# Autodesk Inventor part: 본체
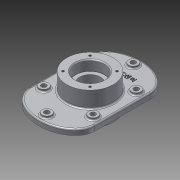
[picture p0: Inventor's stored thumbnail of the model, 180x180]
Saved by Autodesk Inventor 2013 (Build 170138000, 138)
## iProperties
Created: 2015-02
Part Number: 본체
Material: 알루미늄 6061
Document SubType Name: Modeling
Designer: Administrator
Density: 2.71 g/cm^3
Mass: 1660.48 g
Surface Area: 940.405 cm^2
Volume: 612.722 cm^3
Author: Administrator
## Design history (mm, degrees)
sketch "스케치1" dims "d8" = 70, "d10" = 50, "d11" = 50
  geometry: L1 (70, 60)-(70, -60); L2 (-70, -60)-(-70, 60); 5 further points; 2 other entities
  constraints: 4 end point, 2 horizontal alignment, 2 midpoint, 2 vertical alignment, 1 parallel, 8 other
  dimensions: "d5" = 140 distance between parallel lines of L1 L2; "d7" = 120 distance of point (0, 60) point (0, -60); "d133" = 60 distance of point (0, 0) point (0, 60); "d134" = 60 distance of point (0, 0) point (0, -60) (derived)
extrude "돌출1" new body sketch "스케치1" distance "d12" = 12; taper "d13" = 0 deg
sketch "스케치2"
  geometry: C1 r 50 at (0, 0); 1 further point
  constraints: 1 centre point, 1 coincident
  dimensions: "d14" = 100 diameter of C1
extrude "돌출2" join sketch "스케치2" distance "d15" = 35; taper "d16" = 0 deg
sketch "스케치3"
  geometry: C1 r 50 at (0, 0); 1 further point
  constraints: 1 centre point, 1 coincident
  dimensions: "d17" = 100 diameter of C1
extrude "돌출3" join sketch "스케치3" distance "d18" = 23; taper "d19" = 0 deg
sketch "스케치4"
  geometry: L1 (-70, 60)-(-70, -60) reference; L2 (70, -60)-(70, 60) reference; L3 (-53, 60)-(-53, -60); L4 (53, -60)-(53, 60); C1 r 50 at (0, 0) reference; C2 r 10 at (0, 93); C3 r 10 at (-53, 46.5); C4 r 10 at (-53, -46.5); C5 r 10 at (0, -93); C6 r 10 at (53, -46.5); C7 r 10 at (53, 46.5); 2 further points; 2 other entities
  constraints: 6 centre point, 4 end point, 3 parallel, 1 horizontal alignment, 1 vertical alignment, 9 other
  dimensions: "d20" = 17 distance between parallel lines of L2 L4; "d21" = 20 diameter of C2; "d24" = 360 deg dimension on C1.centre C2.centre (derived); "d26" = 17 distance from line of L2 C7.centre; "d27" = 17 distance from line of L2 C6.centre; "d28" = 17 distance from line of L1 C4.centre; "d29" = 17 distance from line of L1 C3.centre
extrude "돌출4" join sketch "스케치4" distance "d30" = 5; taper "d31" = 0 deg
hole "구멍1" diameter "d34" = 11; stored, may be unused: countersink angle "d38" = 90 deg, drill point angle "d40" = 0 deg; dims "d32" = 10, "d33" = 10, "d35" = 6, "d36" = 4, "d37" = 2, "d39" = 8
hole "구멍2" diameter "d43" = 11; stored, may be unused: countersink angle "d47" = 90 deg, drill point angle "d49" = 0 deg; dims "d41" = 10, "d42" = 10, "d44" = 6, "d45" = 4, "d46" = 2, "d48" = 8
hole "구멍3" diameter "d52" = 11; stored, may be unused: countersink angle "d56" = 90 deg, drill point angle "d58" = 0 deg; dims "d50" = 10, "d51" = 10, "d53" = 6, "d54" = 4, "d55" = 2, "d57" = 8
hole "구멍4" diameter "d61" = 11; stored, may be unused: countersink angle "d65" = 90 deg, drill point angle "d67" = 0 deg; dims "d59" = 10, "d60" = 10, "d62" = 6, "d63" = 4, "d64" = 2, "d66" = 8
hole "구멍5" diameter "d70" = 11; stored, may be unused: countersink angle "d74" = 90 deg, drill point angle "d76" = 0 deg; dims "d68" = 10, "d69" = 10, "d71" = 6, "d72" = 4, "d73" = 2, "d75" = 8
hole "구멍6" diameter "d79" = 11; stored, may be unused: countersink angle "d83" = 90 deg, drill point angle "d85" = 0 deg; dims "d77" = 10, "d78" = 10, "d80" = 6, "d81" = 4, "d82" = 2, "d84" = 8
sketch "스케치5"
  geometry: C1 r 50 at (0, 0) reference; C2 r 5.5 at (0, 93) reference; 1 further point
  dimensions: "d86" = 41 distance of point (28.991, 28.991) C1.centre; "d87" = 45 deg dimension on C1.centre point (28.991, 28.991) C2.centre
hole "구멍7" sketch "스케치5" at (28.991, 28.991) diameter "d88" = 4.917; stored, may be unused: countersink angle "d92" = 90 deg, drill point angle "d94" = 118 deg; dims "d89" = 10, "d90" = 4, "d91" = 2, "d93" = 13
sketch "스케치6"
  geometry: C1 r 50 at (0, 0) reference; C2 r 5.5 at (0, 93) reference; 1 further point
  dimensions: "d98" = 41 distance of point (28.991, 28.991) C1.centre; "d99" = 45 deg dimension on C1.centre point (28.991, 28.991) C2.centre
hole "구멍8" sketch "스케치6" at (28.991, 28.991) diameter "d100" = 4.917; stored, may be unused: countersink angle "d104" = 90 deg, drill point angle "d106" = 118 deg; dims "d101" = 10, "d102" = 4, "d103" = 2, "d105" = 13
sketch "스케치7"
  geometry: C1 r 50 at (0, 0) reference
hole "구멍9" sketch "스케치7" at (0, 0) diameter "d110" = 62; stored, may be unused: countersink angle "d114" = 90 deg, drill point angle "d116" = 0 deg; dims "d111" = 10, "d112" = 4, "d113" = 2, "d115" = 22
sketch "스케치8"
  geometry: C1 r 50 at (0, 0) reference
hole "구멍10" sketch "스케치8" at (0, 0) diameter "d117" = 45; stored, may be unused: countersink angle "d121" = 90 deg, drill point angle "d123" = 0 deg; dims "d118" = 10, "d119" = 62, "d120" = 22, "d122" = 22
sketch "스케치9"
  geometry: C1 r 50 at (0, 0) reference; 1 further point
  constraints: 1 vertical alignment, 1 other
  dimensions: "d124" = 65 distance of C1.centre point (0, 65)
feature "엠보싱1" sketch "스케치9" dims "d5" = 140, "d7" = 120, "d8" = 70, "d10" = 50, "d11" = 50, "d22" = 60, "d125" = 1, "d126" = 0, "d133" = 60, "d134" = 60 (derived)
fillet "모깎기1" dims "d127" = 3
fillet "모깎기2" dims "d128" = 3
fillet "모깎기3" dims "d129" = 0.3
chamfer "모따기1" distance "d130" = 2; stored, may be unused: second distance "d131" = 2, angle "d132" = 45 deg
node "솔리드1"
pattern_circular "원형 패턴1" dims angle "d96" = 360 deg
pattern_circular "원형 패턴2" dims angle "d108" = 360 deg
